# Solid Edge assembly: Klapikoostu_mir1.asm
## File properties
Author: Türk
Template: Iso Assembly.asm
Last saved by: Türk
Revision: 3
Application: Solid Edge
Username: Türk
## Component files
Klapp.par
Klapi vedru_mir.par
Klapipuks.par
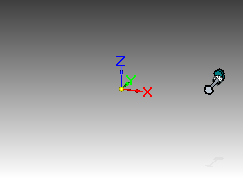
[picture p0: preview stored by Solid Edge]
